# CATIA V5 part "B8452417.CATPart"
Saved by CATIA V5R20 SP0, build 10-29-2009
Part number: B8452417
Revision: 2
Definition: design
Nomenclature: B8452417
Source: made
Description: NOT SPECIFIED
Bounding box of the stored display mesh (mm): x -20.5 to 20.5, y -20.5 to 20.5, z -12 to 17
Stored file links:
  C:\Users\Utente\Desktop\3D files B845\B8452417.CATPart
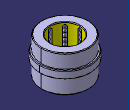
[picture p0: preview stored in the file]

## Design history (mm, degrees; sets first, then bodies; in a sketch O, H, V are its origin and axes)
Body1 "MANIFOLD_SOLID_BREP #38" (main body)
  Solid1: solid without history
Body2 "MANIFOLD_SOLID_BREP #76"
  Solid2: solid without history
Body3 "MANIFOLD_SOLID_BREP #114"
  Solid3: solid without history
Body4 "MANIFOLD_SOLID_BREP #152"
  Solid4: solid without history
Body5 "MANIFOLD_SOLID_BREP #190"
  Solid5: solid without history
Body6 "MANIFOLD_SOLID_BREP #2248"
  Solid6: solid without history
Body7 "MANIFOLD_SOLID_BREP #2286"
  Solid7: solid without history
Body8 "MANIFOLD_SOLID_BREP #2324"
  Solid8: solid without history
Body9 "MANIFOLD_SOLID_BREP #2362"
  Solid9: solid without history
Body10 "MANIFOLD_SOLID_BREP #2400"
  Solid10: solid without history
Body11 "MANIFOLD_SOLID_BREP #2438"
  Solid11: solid without history
Body12 "MANIFOLD_SOLID_BREP #2476"
  Solid12: solid without history
Body13 "MANIFOLD_SOLID_BREP #2514"
  Solid13: solid without history
Body14 "MANIFOLD_SOLID_BREP #2552"
  Solid14: solid without history
Body15 "MANIFOLD_SOLID_BREP #2590"
  Solid15: solid without history
Body16 "MANIFOLD_SOLID_BREP #2628"
  Solid16: solid without history
Body17 "MANIFOLD_SOLID_BREP #2666"
  Solid17: solid without history
Body18 "MANIFOLD_SOLID_BREP #2704"
  Solid18: solid without history
Body19 "MANIFOLD_SOLID_BREP #2742"
  Solid19: solid without history
Body20 "MANIFOLD_SOLID_BREP #2780"
  Solid20: solid without history
Body21 "MANIFOLD_SOLID_BREP #2818"
  Solid21: solid without history
Body22 "MANIFOLD_SOLID_BREP #2856"
  Solid22: solid without history
Body23 "MANIFOLD_SOLID_BREP #2894"
  Solid23: solid without history
Body24 "MANIFOLD_SOLID_BREP #2932"
  Solid24: solid without history
Body25 "MANIFOLD_SOLID_BREP #2970"
  Solid25: solid without history
Body26 "MANIFOLD_SOLID_BREP #3008"
  Solid26: solid without history
Body27 "MANIFOLD_SOLID_BREP #3046"
  Solid27: solid without history
Body28 "MANIFOLD_SOLID_BREP #3084"
  Solid28: solid without history
Body29 "MANIFOLD_SOLID_BREP #3122"
  Solid29: solid without history
Body30 "MANIFOLD_SOLID_BREP #3160"
  Solid30: solid without history
Body31 "MANIFOLD_SOLID_BREP #3198"
  Solid31: solid without history
Body32 "MANIFOLD_SOLID_BREP #3236"
  Solid32: solid without history
Body33 "MANIFOLD_SOLID_BREP #3274"
  Solid33: solid without history
Body34 "MANIFOLD_SOLID_BREP #3312"
  Solid34: solid without history
Body35 "MANIFOLD_SOLID_BREP #3350"
  Solid35: solid without history
Body36 "MANIFOLD_SOLID_BREP #3388"
  Solid36: solid without history
Body37 "MANIFOLD_SOLID_BREP #3426"
  Solid37: solid without history
Body38 "MANIFOLD_SOLID_BREP #3464"
  Solid38: solid without history
Body39 "MANIFOLD_SOLID_BREP #3502"
  Solid39: solid without history
Body40 "MANIFOLD_SOLID_BREP #3540"
  Solid40: solid without history
Body41 "MANIFOLD_SOLID_BREP #3578"
  Solid41: solid without history
Body42 "MANIFOLD_SOLID_BREP #3616"
  Solid42: solid without history
Body43 "MANIFOLD_SOLID_BREP #3654"
  Solid43: solid without history
Body44 "MANIFOLD_SOLID_BREP #3692"
  Solid44: solid without history
Body45 "MANIFOLD_SOLID_BREP #3730"
  Solid45: solid without history
Body46 "MANIFOLD_SOLID_BREP #3768"
  Solid46: solid without history
Body47 "MANIFOLD_SOLID_BREP #3806"
  Solid47: solid without history
Body48 "MANIFOLD_SOLID_BREP #3844"
  Solid48: solid without history
Body49 "MANIFOLD_SOLID_BREP #3882"
  Solid49: solid without history
Body50 "MANIFOLD_SOLID_BREP #3920"
  Solid50: solid without history
Body51 "MANIFOLD_SOLID_BREP #3958"
  Solid51: solid without history
Body52 "MANIFOLD_SOLID_BREP #3996"
  Solid52: solid without history
Body53 "MANIFOLD_SOLID_BREP #4034"
  Solid53: solid without history
Body54 "MANIFOLD_SOLID_BREP #4072"
  Solid54: solid without history
Body55 "MANIFOLD_SOLID_BREP #4110"
  Solid55: solid without history
Body56 "MANIFOLD_SOLID_BREP #4148"
  Solid56: solid without history
Body57 "MANIFOLD_SOLID_BREP #4186"
  Solid57: solid without history
Body58 "MANIFOLD_SOLID_BREP #4224"
  Solid58: solid without history
Body59 "MANIFOLD_SOLID_BREP #4262"
  Solid59: solid without history
Body60 "MANIFOLD_SOLID_BREP #4300"
  Solid60: solid without history
Body61 "MANIFOLD_SOLID_BREP #4338"
  Solid61: solid without history
Body62 "MANIFOLD_SOLID_BREP #4376"
  Solid62: solid without history
Body63 "MANIFOLD_SOLID_BREP #4414"
  Solid63: solid without history
Body64 "MANIFOLD_SOLID_BREP #4452"
  Solid64: solid without history
Body65 "MANIFOLD_SOLID_BREP #4490"
  Solid65: solid without history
